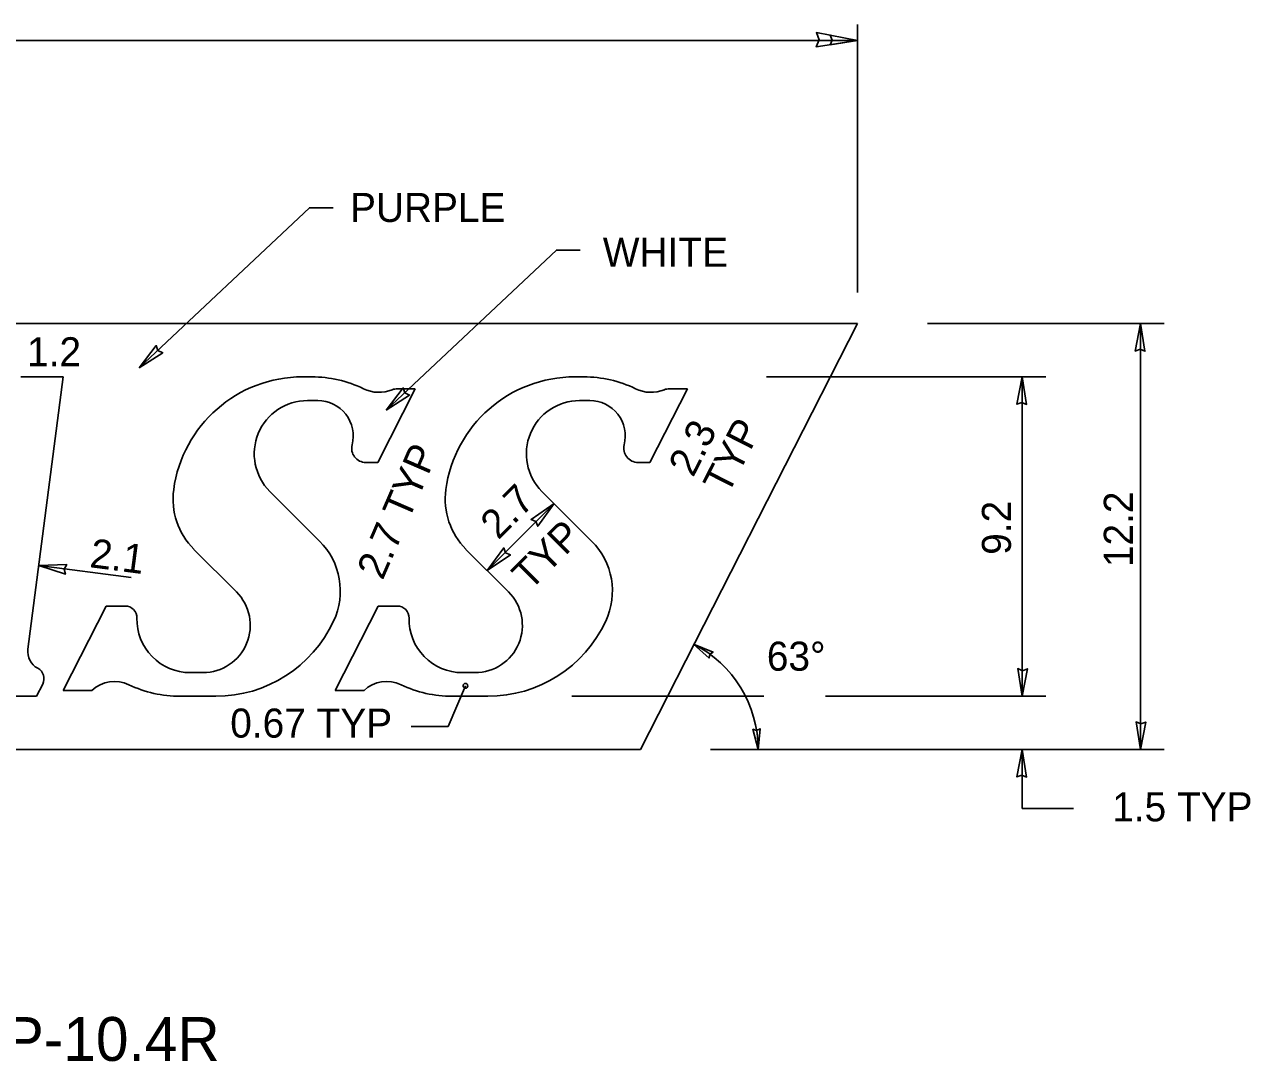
# Model space of a CAD drawing. Extents: x 10268197 to 10269179, y 2141503 to 2142677.
# Drawn here: x 10268704.22 to 10268728.35, y 2142077.2 to 2142097.61 of the extents above; entities that cross this region are included whole.
import ezdxf

# ---------------------------------------------------------------- set-up
doc = ezdxf.new("R2010")
doc.units = 0
doc.layers.add('Default', color=7, linetype='Continuous')
doc.layers.add('TextDetails', color=7, linetype='Continuous')

msp = doc.modelspace()

# ---------------------------------------------------------------- linework, layer by layer
at = {"layer": 'Default'}
for p, q in [((10268720.621, 2142092.334), (10268720.621, 2142097.608)), ((10268679.858, 2142097.295), (10268720.621, 2142097.295)), ((10268720.621, 2142091.721), (10268695.35, 2142091.721)), ((10268716.35, 2142083.337), (10268720.621, 2142091.721)), ((10268721.995, 2142091.721), (10268726.653, 2142091.721)), ((10268726.187, 2142083.338), (10268726.187, 2142091.721)), ((10268704.15, 2142090.673), (10268704.987, 2142090.673)), ((10268704.987, 2142090.673), (10268704.29, 2142085.314)), ((10268709.699, 2142090.673), (10268709.876, 2142090.673)), ((10268715.054, 2142090.673), (10268715.231, 2142090.673)), ((10268718.827, 2142090.673), (10268724.323, 2142090.673)), ((10268723.858, 2142084.386), (10268723.858, 2142090.673)), ((10268711.914, 2142090.44), (10268711.174, 2142088.988)), ((10268711.566, 2142090.44), (10268711.914, 2142090.44)), ((10268717.27, 2142090.44), (10268716.53, 2142088.988)), ((10268716.92, 2142090.44), (10268717.27, 2142090.44)), ((10268709.993, 2142090.207), (10268709.794, 2142090.207)), ((10268715.35, 2142090.207), (10268715.149, 2142090.207)), ((10268711.174, 2142088.988), (10268710.94, 2142088.988)), ((10268716.53, 2142088.988), (10268716.297, 2142088.988)), ((10268709.052, 2142088.418), (10268710.029, 2142087.442)), ((10268714.408, 2142088.418), (10268715.384, 2142087.442)), ((10268713.332, 2142086.86), (10268714.65, 2142088.177)), ((10268708.394, 2142086.441), (10268707.557, 2142087.278)), ((10268713.75, 2142086.441), (10268712.912, 2142087.278)), ((10268704.505, 2142086.962), (10268706.321, 2142086.725)), ((10268704.985, 2142084.502), (10268705.83, 2142086.161)), ((10268705.83, 2142086.161), (10268706.203, 2142086.161)), ((10268710.34, 2142084.502), (10268711.186, 2142086.161)), ((10268711.186, 2142086.161), (10268711.56, 2142086.161)), ((10268707.484, 2142084.851), (10268707.735, 2142084.851)), ((10268712.841, 2142084.851), (10268713.092, 2142084.851)), ((10268704.582, 2142084.625), (10268704.459, 2142084.385)), ((10268712.56, 2142083.791), (10268712.901, 2142084.59)), ((10268704.459, 2142084.385), (10268702.13, 2142084.385)), ((10268705.551, 2142084.502), (10268704.985, 2142084.502)), ((10268707.986, 2142084.385), (10268707.286, 2142084.385)), ((10268710.906, 2142084.502), (10268710.34, 2142084.502)), ((10268713.341, 2142084.385), (10268712.642, 2142084.385)), ((10268714.997, 2142084.386), (10268718.773, 2142084.386)), ((10268719.99, 2142084.386), (10268724.323, 2142084.386)), ((10268711.835, 2142083.791), (10268712.56, 2142083.791)), ((10268694.582, 2142083.337), (10268716.35, 2142083.337)), ((10268717.724, 2142083.338), (10268726.653, 2142083.338)), ((10268723.858, 2142082.174), (10268723.858, 2142083.338)), ((10268723.858, 2142082.174), (10268724.872, 2142082.174))]:
    msp.add_line(p, q, dxfattribs=at)
for points in [[(10268720.621, 2142097.295), (10268719.805, 2142097.166), (10268719.866, 2142097.306), (10268719.81, 2142097.451)], [(10268720.621, 2142097.295), (10268720.077, 2142097.209), (10268720.118, 2142097.302), (10268720.08, 2142097.399)], [(10268726.187, 2142091.721), (10268726.273, 2142091.177), (10268726.18, 2142091.218), (10268726.083, 2142091.18)], [(10268706.477, 2142090.852), (10268706.815, 2142091.287), (10268706.849, 2142091.191), (10268706.943, 2142091.146)], [(10268723.858, 2142090.673), (10268723.944, 2142090.129), (10268723.851, 2142090.17), (10268723.754, 2142090.133)], [(10268711.338, 2142090.019), (10268711.676, 2142090.454), (10268711.71, 2142090.358), (10268711.803, 2142090.313)], [(10268714.65, 2142088.177), (10268714.325, 2142087.731), (10268714.288, 2142087.826), (10268714.193, 2142087.868)], [(10268713.332, 2142086.86), (10268713.656, 2142087.306), (10268713.693, 2142087.211), (10268713.788, 2142087.168)], [(10268704.505, 2142086.962), (10268705.055, 2142086.977), (10268705.002, 2142086.89), (10268705.027, 2142086.788)], [(10268717.392, 2142085.413), (10268717.774, 2142085.256), (10268717.711, 2142085.212), (10268717.697, 2142085.136)], [(10268723.858, 2142084.386), (10268723.773, 2142084.93), (10268723.866, 2142084.889), (10268723.963, 2142084.926)], [(10268726.187, 2142083.338), (10268726.101, 2142083.882), (10268726.195, 2142083.841), (10268726.291, 2142083.878)], [(10268718.663, 2142083.338), (10268718.56, 2142083.738), (10268718.633, 2142083.714), (10268718.702, 2142083.748)], [(10268723.858, 2142083.338), (10268723.944, 2142082.794), (10268723.851, 2142082.835), (10268723.754, 2142082.797)]]:
    msp.add_lwpolyline(points, close=True, dxfattribs=at)
for points in [[(10268710.299, 2142094.002), (10268709.832, 2142094.002), (10268706.477, 2142090.852)], [(10268715.16, 2142093.169), (10268714.693, 2142093.169), (10268711.338, 2142090.019)]]:
    msp.add_lwpolyline(points, dxfattribs=at)
msp.add_circle((10268712.901, 2142084.591), 0.0466, dxfattribs=at)
for centre, radius, start, end in [((10268709.698, 2142088.111), 2.562, 90, 172.3089), ((10268709.875, 2142088.344), 2.329, 64.0896, 90), ((10268715.054, 2142088.111), 2.562, 90, 172.3089), ((10268715.231, 2142088.344), 2.329, 64.0896, 90), ((10268711.198, 2142091.067), 0.699, 244.0896, 292.0347), ((10268711.565, 2142090.16), 0.279, 90, 112.0347), ((10268716.554, 2142091.067), 0.699, 244.0896, 292.0347), ((10268716.92, 2142090.16), 0.279, 90, 112.0347), ((10268709.793, 2142089.159), 1.048, 90, 225), ((10268709.993, 2142089.508), 0.699, 345.6915, 90), ((10268715.149, 2142089.159), 1.048, 90, 225), ((10268715.349, 2142089.508), 0.699, 345.6915, 90), ((10268710.941, 2142089.267), 0.279, 165.6915, 270), ((10268716.297, 2142089.267), 0.279, 165.6915, 270), ((10268708.544, 2142088.267), 1.397, 172.3089, 225), ((10268713.9, 2142088.267), 1.397, 172.3089, 225), ((10268709.041, 2142086.454), 1.397, 334.95, 45), ((10268714.397, 2142086.454), 1.397, 334.95, 45), ((10268707.735, 2142085.782), 0.931, 270, 45), ((10268713.091, 2142085.782), 0.931, 270, 45), ((10268706.204, 2142085.929), 0.233, 358.6664, 90), ((10268711.56, 2142085.929), 0.233, 358.6664, 90), ((10268707.484, 2142085.899), 1.048, 178.6665, 270), ((10268707.986, 2142086.947), 2.562, 270, 334.95), ((10268712.84, 2142085.899), 1.048, 178.6665, 270), ((10268713.342, 2142086.947), 2.562, 270, 334.95), ((10268704.66, 2142085.265), 0.373, 172.5884, 241.8673), ((10268716.334, 2142083.338), 2.329, 0, 63.0012), ((10268704.374, 2142084.731), 0.233, 332.9784, 61.8673), ((10268705.996, 2142084.026), 0.652, 64.3795, 133.1892), ((10268707.285, 2142086.714), 2.329, 244.3795, 270), ((10268711.352, 2142084.026), 0.652, 64.3795, 133.1892), ((10268712.641, 2142086.714), 2.329, 244.3795, 270)]:
    msp.add_arc(centre, radius, start, end, dxfattribs=at)

# ---------------------------------------------------------------- texts
for s, p in [('PURPLE', (10268710.63, 2142093.721)), ('WHITE', (10268715.605, 2142092.839)), ('1.2', (10268704.273, 2142090.881)), ('63°', (10268718.833, 2142084.889)), ('0.67 TYP', (10268708.272, 2142083.572)), ('1.5 TYP', (10268725.631, 2142081.924))]:
    msp.add_text(s, height=0.5717, dxfattribs=at).set_placement(p)
for s, rotation, p in [('2.3', 63, (10268717.382, 2142088.678)), ('TYP', 63, (10268718.065, 2142088.33)), ('2.7 TYP', 66.578, (10268711.271, 2142086.654)), ('2.7', 45, (10268713.548, 2142087.449)), ('12.2', 90, (10268726.037, 2142086.928)), ('9.2', 90, (10268723.638, 2142087.17)), ('TYP', 45, (10268714.17, 2142086.447)), ('2.1', 352.5994, (10268705.49, 2142086.928))]:
    msp.add_text(s, height=0.5717, rotation=rotation, dxfattribs=at).set_placement(p)
at = {"layer": 'TextDetails'}
msp.add_text('LOGO EP-10.4R', height=0.8624, dxfattribs=at).set_placement((10268699.412, 2142077.209))

doc.saveas('drawing.dxf')
